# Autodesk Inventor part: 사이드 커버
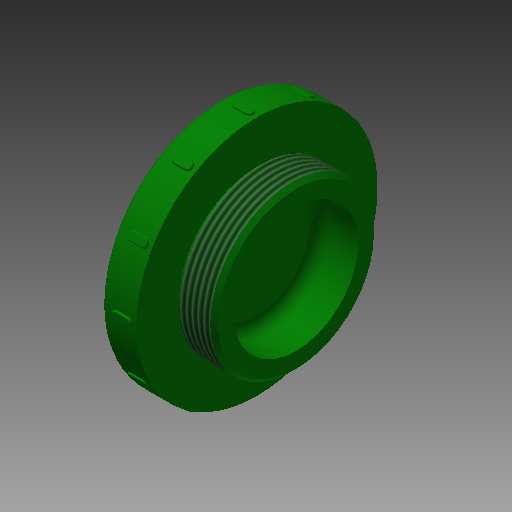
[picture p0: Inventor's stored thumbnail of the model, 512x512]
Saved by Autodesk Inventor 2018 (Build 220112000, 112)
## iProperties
Created: 2016-08
Part Number: 사이드 커버
Material: 스테인리스강
Document SubType Name: Modeling
Designer: mduedu
Density: 8.08 g/cm^3
Appearance: 진녹색
Author: mduedu
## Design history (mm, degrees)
sketch "스케치1"
  geometry: L1 (-5, 0)-(5, 0); L2 (-5, 0)-(-5, 31); L3 (-5, 31)-(5, 31); L4 (5, 31)-(5, 21); L5 (5, 21)-(15, 21); L6 (15, 21)-(15, 16); L7 (15, 16)-(5, 16); L8 (5, 16)-(5, 0); 2 further points
  constraints: 16 end point, 4 parallel, 2 perpendicular, 1 coincident, 1 collinear, 1 horizontal, 1 midpoint, 1 vertical
  dimensions: "d0" = 10 distance of L1.start L1.end; "d2" = 62 diameter of L3 L1; "d3" = 42 diameter of L5 L1; "d4" = 10 distance between parallel lines of L6 L8; "d5" = 5 distance of L5.end L6.end
revolve "회전1" sketch "스케치1" stored, may be unused: angle "d6" = 90 deg
fillet "모깎기1" dims "d7" = 3
sketch "스케치2"
  geometry: L1 (5, -31)-(5, 31) reference; L2 (5, 21)-(15, 21) reference; L3 (0, 0)-(5, 0); L4 (5, 21)-(6, 21); L5 (6, 21)-(6, 20); L6 (6, 20)-(5, 20); L7 (5, 20)-(5, 21)
  constraints: 10 end point, 2 parallel, 1 horizontal, 1 midpoint, 1 perpendicular
  dimensions: "d8" = 1 distance of L2.start L4.end; "d9" = 40 diameter of L6 L3
revolve "회전2" sketch "스케치2" stored, may be unused: angle "d10" = 90 deg
fillet "모깎기2" dims "d11" = 3
feature "스레드1" dims "d12" = 10, "d13" = 0
chamfer "모따기1" distance "d14" = 1; stored, may be unused: second distance "d15" = 2, angle "d16" = 45 deg
node "작업 평면1"
sketch "스케치3"
  geometry: L1 (1, -1)-(-4, -1); L2 (-4, -1)-(-4, 1); L3 (-4, 1)-(1, 1); L4 (1, 1)-(1, -1); 2 further points
  constraints: 8 end point, 2 parallel, 1 horizontal, 1 horizontal alignment, 1 midpoint, 1 perpendicular
  dimensions: "d18" = 2 distance of L3.end L1.start; "d20" = 5 distance of L1.start L1.end; "d21" = 1 distance from line of L4 point (0, 0)
extrude "돌출1" join sketch "스케치3" stored distance "d22" = 10; taper "d23" = 0 deg
fillet "모깎기3" dims "d24" = 1
fillet "모깎기4" dims "d25" = 0.2
sketch "스케치4"
  geometry: 2 further points
  constraints: 1 coincident, 1 other
feature "엠보싱1" sketch "스케치4" dims "d0" = 10, "d2" = 62, "d3" = 42, "d4" = 10, "d5" = 5, "d29" = 0.5, "d30" = 0
node "솔리드1"
pattern_circular "원형 패턴1" dims angle "d27" = 360 deg
other parameters: "d17" = 31.5
